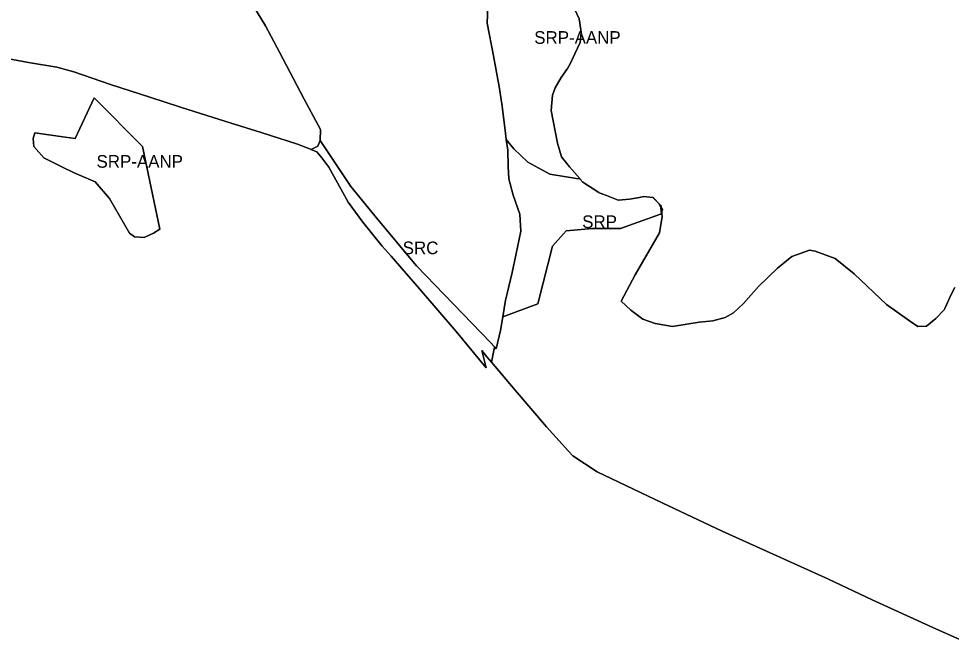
# Model space of a CAD drawing. Extents: x 598968 to 613553, y 4409678 to 4430833.
# Drawn here: x 605173 to 606058, y 4417861 to 4418453 of the extents above; entities that cross this region are included whole.
import ezdxf

# ---------------------------------------------------------------- set-up
doc = ezdxf.new("R2010")
doc.units = 0
for name, color, linetype in [('Nucli Rural', 7, 'Continuous'), ('Sòl Rústic Comú', 7, 'Continuous'), ('Sòl Rústic Protegit', 7, 'Continuous'), ('Sòl Rústic Protegit - Alt Nivell de Protecció', 7, 'Continuous')]:
    doc.layers.add(name, color=color, linetype=linetype)

msp = doc.modelspace()

# ---------------------------------------------------------------- linework, layer by layer
at = {"layer": 'Nucli Rural'}
msp.add_lwpolyline([(605387.46, 4418477.7701), (605406.8485, 4418445.8409), (605420.18, 4418421.0601), (605443.3575, 4418376.4341), (605459.05, 4418347.5801), (605458.66, 4418337.1901), (605487.81, 4418293.3901), (605513.41, 4418262.1301), (605550.16, 4418218.0601), (605620.3215, 4418145.2407), (605624.1249, 4418141.1892), (605625.72, 4418139.4901), (605629.88, 4418156.8401), (605632.0633, 4418169.7835), (605634.7289, 4418185.586), (605636.2822, 4418191.9446), (605640.9988, 4418211.6959), (605644.4574, 4418228.3744), (605649.05, 4418251.1501), (605648.14, 4418267.1101), (605641.9631, 4418285.129), (605637.59, 4418300.5701), (605637.2685, 4418312.449), (605636.85, 4418327.9101), (605635.1666, 4418338.2096), (605634.6757, 4418344.2255), (605632.2872, 4418362.1483), (605631.0058, 4418371.7637), (605630.4641, 4418375.8289), (605629.03, 4418386.5901), (605623.1858, 4418417.3556), (605617.3, 4418448.3401), (605617.7755, 4418464.5778)], dxfattribs=at)
at = {"layer": 'Sòl Rústic Comú'}
msp.add_lwpolyline([(605624.1249, 4418141.1892), (605620.3215, 4418145.2407), (605550.16, 4418218.0601), (605513.41, 4418262.1301), (605487.81, 4418293.3901), (605458.66, 4418337.1901), (605456.4717, 4418331.6576), (605450.1161, 4418328.6958), (605449.9079, 4418328.5354), (605455.6787, 4418326.1958), (605460.3661, 4418320.6958), (605466.8037, 4418311.6958), (605485.2413, 4418278.6958), (605499.0539, 4418259.6958), (605517.4915, 4418236.6958), (605526.1789, 4418227.1958), (605553.0541, 4418196.1958), (605587.7419, 4418155.6958), (605616.1795, 4418121.1958), (605612.1367, 4418137.616), (605616.9551, 4418131.7826), (605621.1953, 4418126.6494), (605623.7817, 4418139.4861)], close=True, dxfattribs=at)
at = {"layer": 'Sòl Rústic Protegit'}
for points in [[(605144.4257, 4418418.1954), (605181.8011, 4418411.1954), (605208.9263, 4418406.6954), (605224.9265, 4418402.1954), (605259.6143, 4418390.1956), (605297.0521, 4418378.1956), (605326.2399, 4418368.6956), (605369.2403, 4418355.1956), (605402.6157, 4418344.6956), (605437.1785, 4418333.6958), (605449.3807, 4418328.749), (605449.9079, 4418328.5354), (605450.1161, 4418328.6958), (605456.4717, 4418331.6576), (605458.66, 4418337.1901), (605459.05, 4418347.5801), (605443.3575, 4418376.4341), (605420.18, 4418421.0601), (605406.8485, 4418445.8409), (605387.46, 4418477.7701)], [(606072.0583, 4417860.6962), (606040.1831, 4417874.6962), (605982.5575, 4417901.196), (605941.0571, 4417920.696), (605882.4317, 4417947.196), (605840.1813, 4417966.196), (605783.3683, 4417993.1958), (605721.6527, 4418022.6792), (605698.6323, 4418037.6514), (605694.3197, 4418042.1512), (605673.6325, 4418065.1508), (605658.7333, 4418082.6792), (605643.8827, 4418100.15), (605621.1953, 4418126.6494), (605616.9551, 4418131.7826), (605612.1367, 4418137.616), (605616.1795, 4418121.1958), (605587.7419, 4418155.6958), (605553.0541, 4418196.1958), (605526.1789, 4418227.1958), (605517.4915, 4418236.6958), (605499.0539, 4418259.6958), (605485.2413, 4418278.6958), (605466.8037, 4418311.6958), (605460.3661, 4418320.6958), (605455.6787, 4418326.1958), (605449.9079, 4418328.5354), (605449.3807, 4418328.749), (605437.1785, 4418333.6958), (605402.6157, 4418344.6956), (605369.2403, 4418355.1956), (605326.2399, 4418368.6956), (605297.0521, 4418378.1956), (605259.6143, 4418390.1956), (605224.9265, 4418402.1954), (605208.9263, 4418406.6954), (605181.8011, 4418411.1954), (605144.4257, 4418418.1954)], [(606061.1175, 4418197.5102), (606057.6175, 4418191.0102), (606051.5551, 4418177.5102), (606050.8677, 4418176.5102), (606043.0551, 4418168.0102), (606033.9927, 4418161.0102), (606025.9301, 4418160.5102), (606017.9301, 4418166.0102), (605996.3051, 4418181.5102), (605965.6177, 4418210.5102), (605947.5551, 4418225.0102), (605928.4301, 4418232.0102), (605922.9301, 4418233.0102), (605906.3051, 4418227.0102), (605892.7427, 4418216.0102), (605874.6177, 4418198.5102), (605860.5551, 4418182.5102), (605850.9925, 4418173.5102), (605842.9925, 4418169.0102), (605831.4299, 4418166.0102), (605818.3677, 4418164.5102), (605793.1801, 4418160.5102), (605776.6177, 4418163.5102), (605765.0551, 4418167.5102), (605753.4927, 4418176.0102), (605744.4301, 4418184.5102), (605757.6801, 4418209.5102), (605780.8051, 4418249.5102), (605783.3051, 4418265.0102), (605783.0551, 4418267.5102), (605782.8347, 4418269.7136), (605783.5189, 4418271.6686), (605782.4589, 4418273.4704), (605782.3051, 4418275.0102), (605780.3149, 4418277.1154), (605774.7425, 4418283.0102), (605774.5221, 4418283.0348), (605779.9417, 4418277.3014), (605782.0859, 4418273.6564), (605782.4615, 4418269.8996), (605782.6819, 4418267.6962), (605781.5469, 4418267.2868), (605743.8689, 4418253.696), (605717.0561, 4418253.696), (605692.1809, 4418251.196), (605679.1181, 4418236.696), (605665.2427, 4418182.1958), (605632.0633, 4418169.7835), (605629.88, 4418156.8401), (605625.72, 4418139.4901), (605624.1249, 4418141.1892), (605623.7817, 4418139.4861), (605621.1953, 4418126.6494), (605643.8827, 4418100.15), (605658.7333, 4418082.6792), (605673.6325, 4418065.1508), (605694.3197, 4418042.1512), (605698.6323, 4418037.6514), (605721.6527, 4418022.6792), (605783.3683, 4417993.1958), (605840.1813, 4417966.196), (605882.4317, 4417947.196), (605941.0571, 4417920.696), (605982.5575, 4417901.196), (606040.1831, 4417874.6962), (606072.0583, 4417860.6962)]]:
    msp.add_lwpolyline(points, dxfattribs=at)
for points in [[(605244.2427, 4418377.5102), (605290.0551, 4418331.5102), (605306.4927, 4418253.0102), (605300.5549, 4418249.0102), (605291.5549, 4418245.0102), (605282.6177, 4418245.5102), (605277.6177, 4418249.0102), (605258.6799, 4418282.0102), (605245.2427, 4418298.0102), (605225.3051, 4418306.5102), (605213.5659, 4418312.2018), (605196.4299, 4418320.5102), (605186.9299, 4418331.5102), (605186.4301, 4418339.0102), (605187.9301, 4418344.5102), (605216.8481, 4418340.3656), (605226.3051, 4418339.0102)], [(605705.0121, 4418300.8784), (605704.8287, 4418300.8442), (605701.8075, 4418301.0526), (605676.7803, 4418305.2236), (605655.9243, 4418316.6942), (605642.3681, 4418329.2078), (605635.1666, 4418338.2096), (605636.85, 4418327.9101), (605637.2685, 4418312.449), (605637.59, 4418300.5701), (605641.9631, 4418285.129), (605648.14, 4418267.1101), (605649.05, 4418251.1501), (605644.4574, 4418228.3744), (605640.9988, 4418211.6959), (605636.2822, 4418191.9446), (605634.7289, 4418185.586), (605632.0633, 4418169.7835), (605665.2427, 4418182.1958), (605679.1181, 4418236.696), (605692.1809, 4418251.196), (605717.0561, 4418253.696), (605743.8689, 4418253.696), (605781.5469, 4418267.2868), (605782.6819, 4418267.6962), (605782.4615, 4418269.8996), (605782.0859, 4418273.6564), (605779.9417, 4418277.3014), (605774.5221, 4418283.0348), (605765.7427, 4418284.0102), (605761.6801, 4418283.0102), (605752.1801, 4418281.5102), (605741.9397, 4418280.5406), (605741.6177, 4418280.5102), (605730.5551, 4418285.0102), (605723.4927, 4418287.5102), (605723.3075, 4418287.6292), (605707.9299, 4418297.5102), (605705.2027, 4418300.6582)]]:
    msp.add_lwpolyline(points, close=True, dxfattribs=at)
at = {"layer": 'Sòl Rústic Protegit - Alt Nivell de Protecció'}
for points in [[(605617.7755, 4418464.5778), (605617.3, 4418448.3401), (605623.1858, 4418417.3556), (605629.03, 4418386.5901), (605630.4641, 4418375.8289), (605631.0058, 4418371.7637), (605632.2872, 4418362.1483), (605634.6757, 4418344.2255), (605635.1666, 4418338.2096), (605642.3681, 4418329.2078), (605655.9243, 4418316.6942), (605676.7803, 4418305.2236), (605701.8075, 4418301.0526), (605704.8287, 4418300.8442), (605705.0121, 4418300.8784), (605695.3675, 4418312.0102), (605687.8051, 4418321.5102), (605683.8049, 4418334.5102), (605677.8051, 4418365.5102), (605679.3049, 4418380.0102), (605681.8051, 4418387.0102), (605687.3049, 4418397.0102), (605693.3677, 4418405.5102), (605695.8677, 4418410.0102), (605700.4301, 4418419.5102), (605705.4301, 4418430.0102), (605706.0607, 4418436.3162), (605706.4301, 4418440.0102), (605706.0607, 4418442.3188), (605704.4299, 4418452.5102), (605691.8675, 4418480.0102)], [(605691.8675, 4418480.0102), (605704.4299, 4418452.5102), (605706.0607, 4418442.3188), (605706.4301, 4418440.0102), (605706.0607, 4418436.3162), (605705.4301, 4418430.0102), (605700.4301, 4418419.5102), (605695.8677, 4418410.0102), (605693.3677, 4418405.5102), (605687.3049, 4418397.0102), (605681.8051, 4418387.0102), (605679.3049, 4418380.0102), (605677.8051, 4418365.5102), (605683.8049, 4418334.5102), (605687.8051, 4418321.5102), (605695.3675, 4418312.0102), (605705.0121, 4418300.8784), (605705.2027, 4418300.6582), (605707.9299, 4418297.5102), (605723.3075, 4418287.6292), (605723.4927, 4418287.5102), (605730.5551, 4418285.0102), (605741.6177, 4418280.5102), (605741.9397, 4418280.5406), (605752.1801, 4418281.5102), (605761.6801, 4418283.0102), (605765.7427, 4418284.0102), (605774.5221, 4418283.0348), (605774.7425, 4418283.0102), (605780.3149, 4418277.1154), (605782.3051, 4418275.0102), (605782.4589, 4418273.4704), (605783.5189, 4418271.6686), (605782.8347, 4418269.7136), (605783.0551, 4418267.5102), (605783.3051, 4418265.0102), (605780.8051, 4418249.5102), (605757.6801, 4418209.5102), (605744.4301, 4418184.5102), (605753.4927, 4418176.0102), (605765.0551, 4418167.5102), (605776.6177, 4418163.5102), (605793.1801, 4418160.5102), (605818.3677, 4418164.5102), (605831.4299, 4418166.0102), (605842.9925, 4418169.0102), (605850.9925, 4418173.5102), (605860.5551, 4418182.5102), (605874.6177, 4418198.5102), (605892.7427, 4418216.0102), (605906.3051, 4418227.0102), (605922.9301, 4418233.0102), (605928.4301, 4418232.0102), (605947.5551, 4418225.0102), (605965.6177, 4418210.5102), (605996.3051, 4418181.5102), (606017.9301, 4418166.0102), (606025.9301, 4418160.5102), (606033.9927, 4418161.0102), (606043.0551, 4418168.0102), (606050.8677, 4418176.5102), (606051.5551, 4418177.5102), (606057.6175, 4418191.0102), (606061.1175, 4418197.5102)]]:
    msp.add_lwpolyline(points, dxfattribs=at)
msp.add_lwpolyline([(605244.2427, 4418377.5102), (605226.3051, 4418339.0102), (605216.8481, 4418340.3656), (605187.9301, 4418344.5102), (605186.4301, 4418339.0102), (605186.9299, 4418331.5102), (605196.4299, 4418320.5102), (605213.5659, 4418312.2018), (605225.3051, 4418306.5102), (605245.2427, 4418298.0102), (605258.6799, 4418282.0102), (605277.6177, 4418249.0102), (605282.6177, 4418245.5102), (605291.5549, 4418245.0102), (605300.5549, 4418249.0102), (605306.4927, 4418253.0102), (605290.0551, 4418331.5102)], close=True, dxfattribs=at)

# ---------------------------------------------------------------- texts
at = {"layer": 'Sòl Rústic Comú'}
msp.add_text('SRC', height=12, dxfattribs=at).set_placement((605537.0164, 4418229.193))
at = {"layer": 'Sòl Rústic Protegit'}
msp.add_text('SRP', height=12, dxfattribs=at).set_placement((605707.3726, 4418253.9966))
at = {"layer": 'Sòl Rústic Protegit - Alt Nivell de Protecció'}
for p in [(605661.8651, 4418428.8986), (605246.4614, 4418311.2602)]:
    msp.add_text('SRP-AANP', height=12, dxfattribs=at).set_placement(p)

doc.saveas('drawing.dxf')
